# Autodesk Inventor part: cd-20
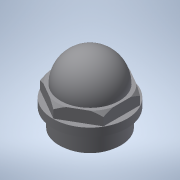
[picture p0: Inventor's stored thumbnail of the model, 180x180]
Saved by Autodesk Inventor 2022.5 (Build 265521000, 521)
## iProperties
Created: 2016-12
Part Number: cd-20
Material: 一般
Document SubType Name: Modeling
Designer: imaocorp
Density: 1 g/cm^3
Appearance: 既定
Author: imaocorp
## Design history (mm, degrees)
node "cd-20.x_t1"
node "cd-20"
node "Base1"
